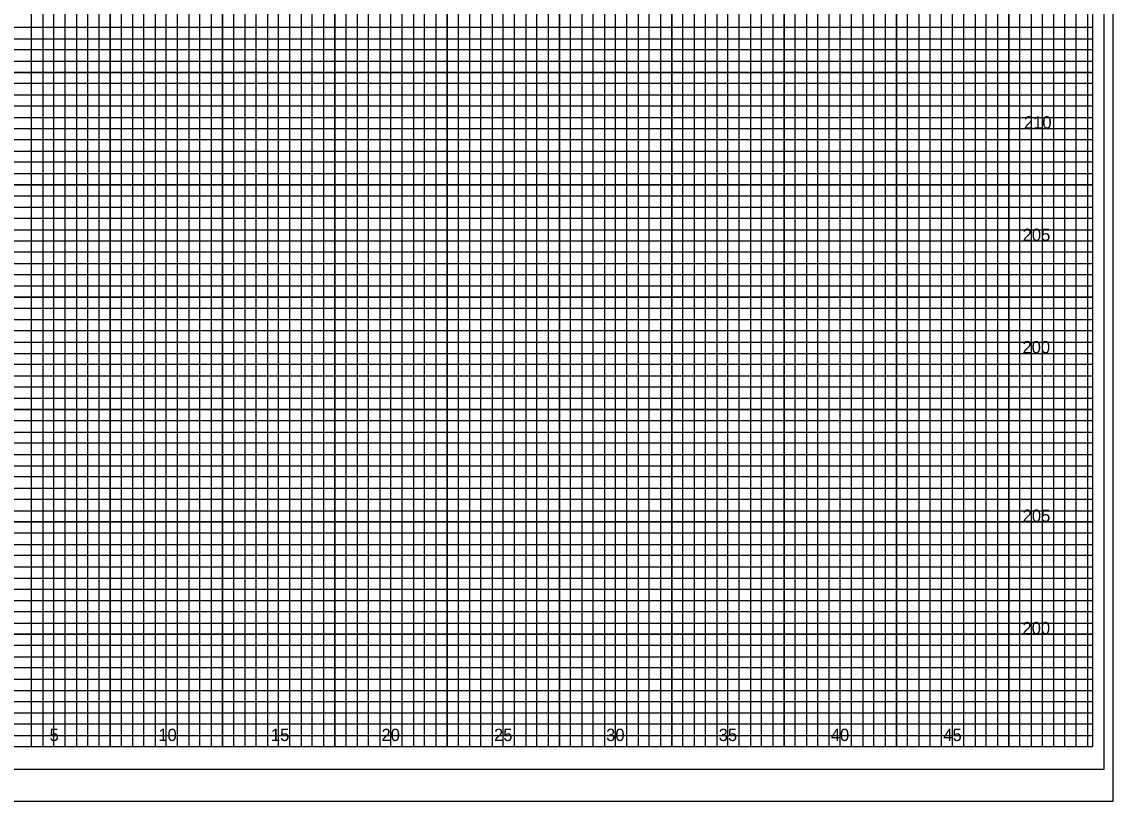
# Model space of a CAD drawing. Extents: x -4 to 103, y -2 to 138.
# Drawn here: x 54.82 to 103.4, y 68.4 to 103.08 of the extents above; entities that cross this region are included whole.
import ezdxf

# ---------------------------------------------------------------- set-up
doc = ezdxf.new("R2010")
doc.units = 0
for name, color, linetype in [('Exist XS Ground Line', 7, 'Continuous'), ('Old_Level_10', 7, 'Continuous'), ('Old_Level_16', 7, 'Continuous'), ('Old_Level_3', 7, 'Continuous'), ('Old_Level_5', 7, 'Continuous'), ('Old_Level_8', 7, 'Continuous'), ('Prop XS Dump Level', 7, 'Continuous'), ('Prop XS Elevation Labels', 7, 'Continuous'), ('Prop XS Finish Grade', 7, 'Continuous')]:
    doc.layers.add(name, color=color, linetype=linetype)

msp = doc.modelspace()

# ---------------------------------------------------------------- linework, layer by layer
at = {"layer": 'Exist XS Ground Line'}
msp.add_lwpolyline([(103, 136.825), (-2.8, 136.825), (-2.8, 69.825), (103, 69.825)], close=True, dxfattribs=at)
at = {"layer": 'Old_Level_10'}
for p, q in [((56.25, 70.825), (56.25, 135.825)), ((58.75, 70.825), (58.75, 135.825)), ((61.25, 70.825), (61.25, 135.825)), ((63.75, 70.825), (63.75, 135.825)), ((66.25, 70.825), (66.25, 135.825)), ((68.75, 70.825), (68.75, 135.825)), ((71.25, 70.825), (71.25, 135.825)), ((73.75, 70.825), (73.75, 135.825)), ((91.25, 70.825), (91.25, 134.25)), ((93.75, 70.825), (93.75, 134.25)), ((96.25, 70.825), (96.25, 134.25)), ((98.75, 70.825), (98.75, 134.25)), ((101.25, 70.825), (101.25, 134.25)), ((76.25, 70.825), (76.25, 132.825)), ((78.75, 70.825), (78.75, 132.825)), ((81.25, 70.825), (81.25, 132.825)), ((83.75, 70.825), (83.75, 132.825)), ((86.25, 70.825), (86.25, 132.825)), ((88.75, 70.825), (88.75, 132.825)), ((0, 100.825), (102.5, 100.825)), ((0, 98.325), (102.5, 98.325)), ((0, 95.825), (102.5, 95.825)), ((0, 93.325), (102.5, 93.325)), ((0, 90.825), (102.5, 90.825)), ((0, 88.325), (102.5, 88.325)), ((0, 85.825), (102.5, 85.825)), ((0, 83.325), (102.5, 83.325)), ((0, 80.825), (102.5, 80.825)), ((0, 78.325), (102.5, 78.325)), ((0, 75.825), (102.5, 75.825)), ((0, 73.325), (102.5, 73.325))]:
    msp.add_line(p, q, dxfattribs=at)
at = {"layer": 'Old_Level_3'}
msp.add_line((-3.5, 68.4), (103.4, 68.4), dxfattribs=at)
at = {"layer": 'Old_Level_5'}
msp.add_lwpolyline([(103.4, 138.225), (-3.5, 138.225), (-3.5, 68.4), (103.4, 68.4)], close=True, dxfattribs=at)
at = {"layer": 'Old_Level_8'}
for points in [[(56.25, 70.825), (56.25, 135.825)], [(58.75, 135.825), (58.75, 70.825), (61.25, 70.825), (61.25, 135.825)], [(63.75, 135.825), (63.75, 70.825), (66.25, 70.825), (66.25, 135.825)], [(68.75, 135.825), (68.75, 70.825), (71.25, 70.825), (71.25, 135.825)], [(73.75, 135.825), (73.75, 70.825), (76.25, 70.825), (76.25, 132.825)], [(88.75, 132.825), (88.75, 70.825), (91.25, 70.825), (91.25, 134.25)], [(93.75, 134.25), (93.75, 70.825), (96.25, 70.825), (96.25, 134.25)], [(98.75, 134.25), (98.75, 70.825), (101.25, 70.825), (101.25, 134.25)], [(78.75, 132.825), (78.75, 70.825), (81.25, 70.825), (81.25, 132.825)], [(83.75, 132.825), (83.75, 70.825), (86.25, 70.825), (86.25, 132.825)], [(0, 98.325), (102.5, 98.325), (102.5, 100.825), (0, 100.825)], [(0, 93.325), (102.5, 93.325), (102.5, 95.825), (0, 95.825)], [(0, 88.325), (102.5, 88.325), (102.5, 90.825), (0, 90.825)], [(0, 83.325), (102.5, 83.325), (102.5, 85.825), (0, 85.825)], [(0, 78.325), (102.5, 78.325), (102.5, 80.825), (0, 80.825)], [(0, 73.325), (102.5, 73.325), (102.5, 75.825), (0, 75.825)]]:
    msp.add_lwpolyline(points, dxfattribs=at)
at = {"layer": 'Prop XS Elevation Labels'}
msp.add_lwpolyline([(102.5, 135.825), (0, 135.825), (0, 70.825), (102.5, 70.825)], close=True, dxfattribs=at)
at = {"layer": 'Prop XS Finish Grade'}
for points in [[(54.75, 70.825), (55.25, 70.825), (55.25, 135.825)], [(55.75, 135.825), (55.75, 70.825), (56.75, 70.825), (56.75, 135.825)], [(57.25, 135.825), (57.25, 70.825), (57.75, 70.825), (57.75, 135.825)], [(58.25, 135.825), (58.25, 70.825), (59.25, 70.825), (59.25, 135.825)], [(59.75, 135.825), (59.75, 70.825), (60.25, 70.825), (60.25, 135.825)], [(60.75, 135.825), (60.75, 70.825), (61.75, 70.825), (61.75, 135.825)], [(62.25, 135.825), (62.25, 70.825), (62.75, 70.825), (62.75, 135.825)], [(63.25, 135.825), (63.25, 70.825), (64.25, 70.825), (64.25, 135.825)], [(64.75, 135.825), (64.75, 70.825), (65.25, 70.825), (65.25, 135.825)], [(65.75, 135.825), (65.75, 70.825), (66.75, 70.825), (66.75, 135.825)], [(67.25, 135.825), (67.25, 70.825), (67.75, 70.825), (67.75, 135.825)], [(68.25, 135.825), (68.25, 70.825), (69.25, 70.825), (69.25, 135.825)], [(69.75, 135.825), (69.75, 70.825), (70.25, 70.825), (70.25, 135.825)], [(70.75, 135.825), (70.75, 70.825), (71.75, 70.825), (71.75, 135.825)], [(72.25, 135.825), (72.25, 70.825), (72.75, 70.825), (72.75, 135.825)], [(73.25, 135.825), (73.25, 70.825), (74.25, 70.825), (74.25, 132.825)], [(89.75, 132.825), (89.75, 70.825), (90.25, 70.825), (90.25, 134.25)], [(90.75, 134.25), (90.75, 70.825), (91.75, 70.825), (91.75, 134.25)], [(92.25, 134.25), (92.25, 70.825), (92.75, 70.825), (92.75, 134.25)], [(93.25, 134.25), (93.25, 70.825), (94.25, 70.825), (94.25, 134.25)], [(94.75, 134.25), (94.75, 70.825), (95.25, 70.825), (95.25, 134.25)], [(95.75, 134.25), (95.75, 70.825), (96.75, 70.825), (96.75, 134.25)], [(97.25, 134.25), (97.25, 70.825), (97.75, 70.825), (97.75, 134.25)], [(98.25, 134.25), (98.25, 70.825), (99.25, 70.825), (99.25, 134.25)], [(99.75, 134.25), (99.75, 70.825), (100.25, 70.825), (100.25, 134.25)], [(100.25, 134.25), (100.75, 134.25), (100.75, 70.825), (101.75, 70.825), (101.75, 134.25), (102.25, 134.25), (102.25, 70.825)], [(74.75, 132.825), (74.75, 70.825), (75.25, 70.825), (75.25, 132.825)], [(75.75, 132.825), (75.75, 70.825), (76.75, 70.825), (76.75, 132.825)], [(77.25, 132.825), (77.25, 70.825), (77.75, 70.825), (77.75, 132.825)], [(78.25, 132.825), (78.25, 70.825), (79.25, 70.825), (79.25, 132.825)], [(79.75, 132.825), (79.75, 70.825), (80.25, 70.825), (80.25, 132.825)], [(80.75, 132.825), (80.75, 70.825), (81.75, 70.825), (81.75, 132.825)], [(82.25, 132.825), (82.25, 70.825), (82.75, 70.825), (82.75, 132.825)], [(83.25, 132.825), (83.25, 70.825), (84.25, 70.825), (84.25, 132.825)], [(84.75, 132.825), (84.75, 70.825), (85.25, 70.825), (85.25, 132.825)], [(85.75, 132.825), (85.75, 70.825), (86.75, 70.825), (86.75, 132.825)], [(87.25, 132.825), (87.25, 70.825), (87.75, 70.825), (87.75, 132.825)], [(88.25, 132.825), (88.25, 70.825), (89.25, 70.825), (89.25, 132.825)], [(0, 102.325), (102.5, 102.325), (102.5, 102.825), (0, 102.825)], [(0, 101.325), (102.5, 101.325), (102.5, 101.825), (0, 101.825)], [(0, 99.825), (102.5, 99.825), (102.5, 100.325), (0, 100.325)], [(0, 98.825), (102.5, 98.825), (102.5, 99.325), (0, 99.325)], [(0, 97.325), (102.5, 97.325), (102.5, 97.825), (0, 97.825)], [(0, 96.325), (102.5, 96.325), (102.5, 96.825), (0, 96.825)], [(0, 94.825), (102.5, 94.825), (102.5, 95.325), (0, 95.325)], [(0, 93.825), (102.5, 93.825), (102.5, 94.325), (0, 94.325)], [(0, 92.325), (102.5, 92.325), (102.5, 92.825), (0, 92.825)], [(0, 91.325), (102.5, 91.325), (102.5, 91.825), (0, 91.825)], [(0, 89.825), (102.5, 89.825), (102.5, 90.325), (0, 90.325)], [(0, 88.825), (102.5, 88.825), (102.5, 89.325), (0, 89.325)], [(0, 87.325), (102.5, 87.325), (102.5, 87.825), (0, 87.825)], [(0, 86.325), (102.5, 86.325), (102.5, 86.825), (0, 86.825)], [(0, 84.825), (102.5, 84.825), (102.5, 85.325), (0, 85.325)], [(0, 83.825), (102.5, 83.825), (102.5, 84.325), (0, 84.325)], [(0, 82.325), (102.5, 82.325), (102.5, 82.825), (0, 82.825)], [(0, 81.325), (102.5, 81.325), (102.5, 81.825), (0, 81.825)], [(0, 79.825), (102.5, 79.825), (102.5, 80.325), (0, 80.325)], [(0, 78.825), (102.5, 78.825), (102.5, 79.325), (0, 79.325)], [(0, 77.325), (102.5, 77.325), (102.5, 77.825), (0, 77.825)], [(0, 76.325), (102.5, 76.325), (102.5, 76.825), (0, 76.825)], [(0, 74.825), (102.5, 74.825), (102.5, 75.325), (0, 75.325)], [(0, 73.825), (102.5, 73.825), (102.5, 74.325), (0, 74.325)], [(0, 72.325), (102.5, 72.325), (102.5, 72.825), (0, 72.825)], [(0, 71.325), (102.5, 71.325), (102.5, 71.825), (0, 71.825)]]:
    msp.add_lwpolyline(points, dxfattribs=at)

# ---------------------------------------------------------------- texts
at = {"layer": 'Old_Level_16'}
for s, p in [('5', (56.057, 71.075)), ('10', (60.897, 71.075)), ('15', (65.906, 71.075)), ('20', (70.831, 71.075)), ('25', (75.84, 71.075)), ('30', (80.831, 71.075)), ('35', (85.84, 71.075)), ('40', (90.831, 71.075)), ('45', (95.84, 71.075))]:
    msp.add_text(s, height=0.55, dxfattribs=at).set_placement(p)
at = {"layer": 'Prop XS Dump Level'}
for s, p in [('210', (99.43, 98.325)), ('205', (99.372, 93.325)), ('200', (99.364, 88.325)), ('205', (99.372, 80.825)), ('200', (99.364, 75.825))]:
    msp.add_text(s, height=0.55, dxfattribs=at).set_placement(p)

doc.saveas('drawing.dxf')
